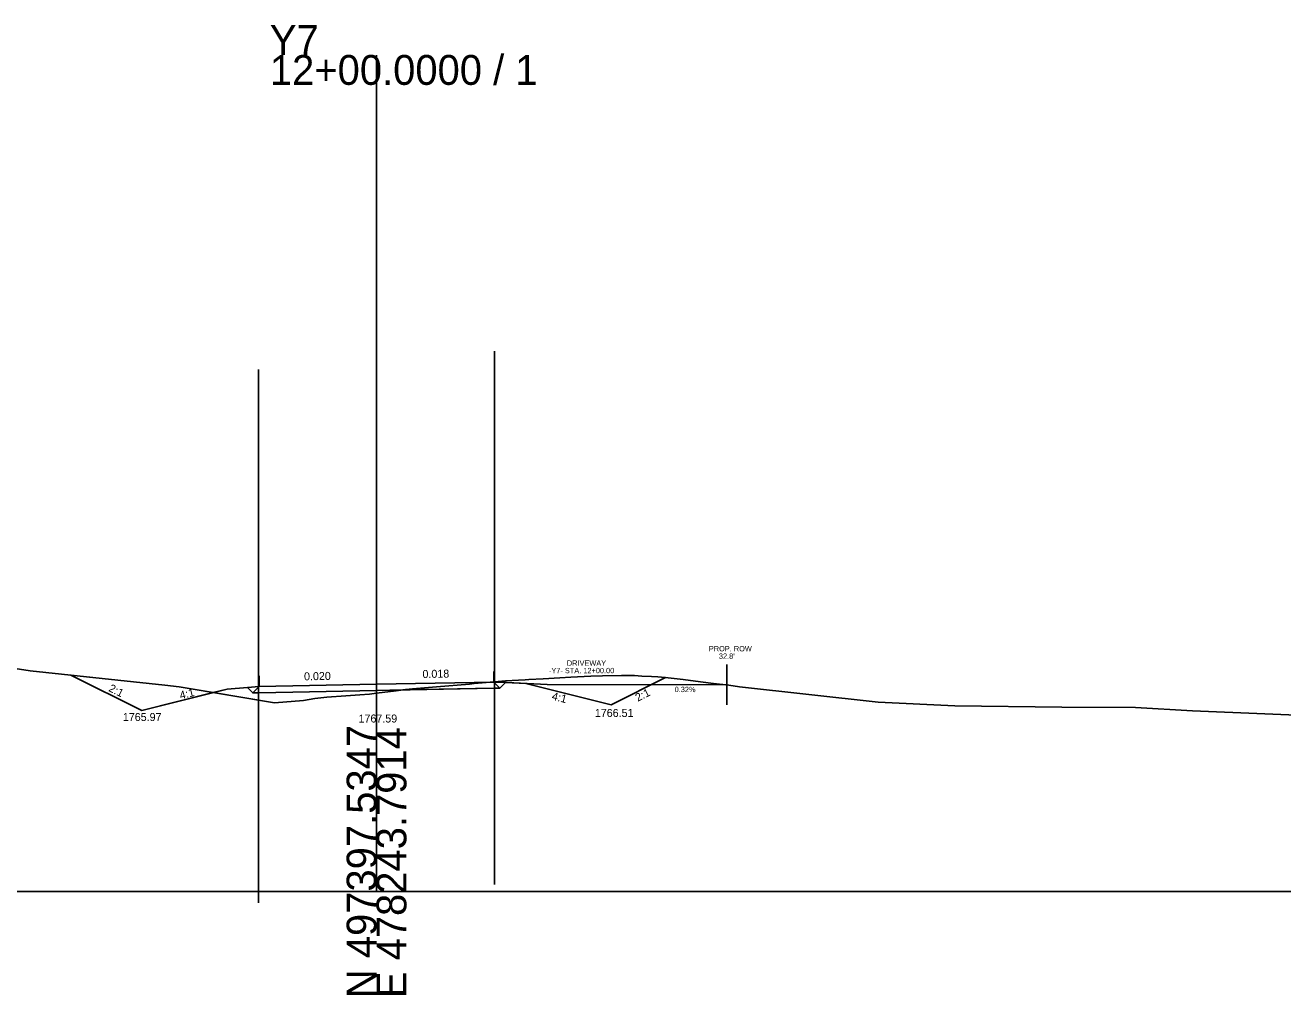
# Model space of a CAD drawing. Extents: x -26 to 403, y -10 to 4071.
# Drawn here: x 167.1 to 285, y 1990.3 to 2081.2 of the extents above; entities that cross this region are included whole.
import ezdxf

# ---------------------------------------------------------------- set-up
doc = ezdxf.new("R2010")
doc.units = 0
for name, color, linetype in [('Exist Cross Section Cell', 7, 'Continuous'), ('Exist XS Center Line Elevation Label', 7, 'Continuous'), ('Exist XS Ground Line', 7, 'Continuous'), ('Prop Road Sect_ Boring - Header (ID Tx)', 7, 'Continuous'), ('Prop Road Sect_ Boring - Material (Outline)', 7, 'Continuous'), ('Prop XS Ditch Slope Text', 7, 'Continuous'), ('Prop XS Ditch Standard Text', 7, 'Continuous'), ('Prop XS Dump Level', 7, 'Continuous'), ('Prop XS Earthwork Shape', 7, 'Continuous'), ('Prop XS EOT Tick Mark', 7, 'Continuous'), ('Prop XS Finish Grade', 7, 'Continuous'), ('Prop XS Finish Grade Earthwork', 7, 'Continuous'), ('Prop XS Finish Grade Pavement', 7, 'Continuous'), ('Prop XS Pvmt Edge Slope', 7, 'Continuous'), ('Prop XS SE Text', 7, 'Continuous'), ('Prop XS Side Slope Text', 7, 'Continuous'), ('Prop XS Subgrade Earthwork', 7, 'Continuous'), ('Scratch_Level_2', 7, 'Continuous')]:
    doc.layers.add(name, color=color, linetype=linetype)

msp = doc.modelspace()

# ---------------------------------------------------------------- linework, layer by layer
at = {"layer": 'Exist Cross Section Cell'}
for p, q in [((200, 2000), (200, 2078.42)), ((0, 2000), (200, 2000)), ((200, 2000), (400, 2000))]:
    msp.add_line(p, q, dxfattribs=at)
at = {"layer": 'Exist XS Ground Line'}
msp.add_lwpolyline([(157.4, 2022.26), (167.53, 2020.7), (180.14, 2019.35), (181.49, 2019.19), (190.45, 2017.67), (193.16, 2017.91), (194.22, 2018.08), (195.35, 2018.23), (197.11, 2018.34), (198.42, 2018.43), (199.33, 2018.51), (200, 2018.59), (201.83, 2018.82), (202.72, 2018.92), (203.36, 2018.99), (205.62, 2019.18), (208.72, 2019.45), (209.15, 2019.49), (211.41, 2019.68), (212.1, 2019.74), (213.32, 2019.81), (213.93, 2019.84), (214.29, 2019.86), (215.61, 2019.93), (217.17, 2020.02), (218.21, 2020.1), (220.08, 2020.17), (221.19, 2020.22), (222.95, 2020.24), (223.26, 2020.25), (223.63, 2020.26), (224.18, 2020.25), (224.88, 2020.19), (225.78, 2020.14), (226.38, 2020.12), (227.06, 2020.06), (228.75, 2019.86), (230.37, 2019.65), (231.58, 2019.51), (233.03, 2019.33), (234.03, 2019.18), (247.01, 2017.76), (254.19, 2017.4), (264.25, 2017.29), (271.14, 2017.25), (276.49, 2016.94), (290.78, 2016.35)], dxfattribs=at)
at = {"layer": 'Prop Road Sect_ Boring - Header (ID Tx)'}
for points in [[(211, 2019.63), (212.1, 2019.58), (211.57, 2019.06)], [(189, 2019.21), (187.9, 2019.12), (188.4, 2018.61)]]:
    msp.add_lwpolyline(points, close=True, dxfattribs=at)
at = {"layer": 'Prop Road Sect_ Boring - Material (Outline)'}
for p, q in [((232.84, 2021.28), (232.84, 2017.49)), ((211, 2019.65), (216, 2019.41)), ((216, 2019.41), (232.84, 2019.36))]:
    msp.add_line(p, q, dxfattribs=at)
at = {"layer": 'Prop XS Dump Level'}
for p, q in [((200, 2019.43), (211, 2019.63)), ((189, 2019.21), (200, 2019.43))]:
    msp.add_line(p, q, dxfattribs=at)
at = {"layer": 'Prop XS Earthwork Shape'}
for points in [[(178, 2016.97), (171.35, 2020.29), (180.14, 2019.35), (181.49, 2019.19), (184.69, 2018.64)], [(212.1, 2019.58), (214, 2019.51), (222, 2017.51), (227.09, 2020.05), (227.06, 2020.06), (226.38, 2020.12), (225.78, 2020.14), (224.88, 2020.19), (224.18, 2020.25), (223.63, 2020.26), (223.26, 2020.25), (222.95, 2020.24), (221.19, 2020.22), (220.08, 2020.17), (218.21, 2020.1), (217.17, 2020.02), (215.61, 2019.93), (214.29, 2019.86), (213.93, 2019.84), (213.32, 2019.81), (212.1, 2019.74), (211.41, 2019.68), (209.15, 2019.49), (208.72, 2019.45), (205.62, 2019.18), (203.36, 2018.99), (202.72, 2018.92), (202.45, 2018.89), (211, 2019.05), (211.57, 2019.06)], [(188.4, 2018.61), (187.9, 2019.12), (186, 2018.97), (184.69, 2018.64), (190.45, 2017.67), (193.16, 2017.91), (194.22, 2018.08), (195.35, 2018.23), (197.11, 2018.34), (198.42, 2018.43), (199.33, 2018.51), (200, 2018.59), (201.83, 2018.82), (202.45, 2018.89), (200, 2018.85), (189, 2018.63)]]:
    msp.add_lwpolyline(points, close=True, dxfattribs=at)
at = {"layer": 'Prop XS EOT Tick Mark'}
for p, q in [((211, 2019.63), (211, 2020.63)), ((189, 2019.21), (189, 2020.21))]:
    msp.add_line(p, q, dxfattribs=at)
at = {"layer": 'Prop XS Finish Grade'}
for p, q in [((211, 2019.63), (212.1, 2019.58)), ((189, 2019.21), (187.9, 2019.12))]:
    msp.add_line(p, q, dxfattribs=at)
at = {"layer": 'Prop XS Finish Grade Earthwork'}
for p, q in [((178, 2016.97), (171.35, 2020.29)), ((212.1, 2019.58), (214, 2019.51)), ((214, 2019.51), (222, 2017.51)), ((222, 2017.51), (227.09, 2020.05)), ((186, 2018.97), (178, 2016.97)), ((187.9, 2019.12), (186, 2018.97))]:
    msp.add_line(p, q, dxfattribs=at)
at = {"layer": 'Prop XS Finish Grade Pavement'}
for p, q in [((200, 2019.43), (211, 2019.63)), ((189, 2019.21), (200, 2019.43))]:
    msp.add_line(p, q, dxfattribs=at)
at = {"layer": 'Prop XS Pvmt Edge Slope'}
for p, q in [((211, 2019.63), (211.57, 2019.06)), ((189, 2019.21), (188.4, 2018.61))]:
    msp.add_line(p, q, dxfattribs=at)
at = {"layer": 'Prop XS Subgrade Earthwork'}
for p, q in [((211.57, 2019.06), (212.1, 2019.58)), ((188.4, 2018.61), (187.9, 2019.12)), ((189, 2018.63), (188.4, 2018.61)), ((200, 2018.85), (189, 2018.63)), ((211, 2019.05), (200, 2018.85)), ((211, 2019.05), (211.57, 2019.06))]:
    msp.add_line(p, q, dxfattribs=at)
at = {"layer": 'Scratch_Level_2'}
for p, q in [((211.07, 2050.65), (211.07, 2000.65)), ((188.93, 2048.92), (188.93, 1998.92))]:
    msp.add_line(p, q, dxfattribs=at)

# ---------------------------------------------------------------- texts
at = {"layer": 'Exist Cross Section Cell'}
for s, p in [('Y7', (190, 2078.42)), ('12+00.0000 / 1', (190, 2075.62))]:
    msp.add_text(s, height=2.8, dxfattribs=at).set_placement(p)
for s, p in [('N 497397.5347', (200, 1990)), ('E 478243.7914', (202.8, 1990))]:
    msp.add_text(s, height=2.8, rotation=90, dxfattribs=at).set_placement(p)
at = {"layer": 'Exist XS Center Line Elevation Label'}
msp.add_text('1767.59', height=0.75, dxfattribs=at).set_placement((198.31, 2015.84))
at = {"layer": 'Prop Road Sect_ Boring - Material (Outline)'}
for s, p in [('PROP. ROW', (231.15, 2022.51)), ("32.8'", (232.09, 2021.81)), ('-Y7- STA. 12+00.00', (216.16, 2020.46)), ('DRIVEWAY', (217.84, 2021.16))]:
    msp.add_text(s, height=0.5, dxfattribs=at).set_placement(p)
msp.add_text('0.32%', height=0.5, rotation=359.8155, dxfattribs=at).set_placement((227.94, 2018.69))
at = {"layer": 'Prop XS Ditch Slope Text'}
for rotation, p in [(14.0362, (181.64, 2018)), (345.9638, (216.38, 2017.99))]:
    msp.add_text('4:1', height=0.75, rotation=rotation, dxfattribs=at).set_placement(p)
at = {"layer": 'Prop XS Ditch Standard Text'}
for s, p in [('1766.51', (220.46, 2016.36)), ('1765.97', (176.22, 2015.98))]:
    msp.add_text(s, height=0.75, dxfattribs=at).set_placement(p)
at = {"layer": 'Prop XS Dump Level'}
for p in [(214, 2019.47), (186, 2018.93)]:
    msp.add_text('Case1', height=0.04, dxfattribs=at).set_placement(p)
at = {"layer": 'Prop XS SE Text'}
for s, rotation, p in [('0.018', 1.0503, (204.31, 2020.01)), ('0.020', 1.1458, (193.21, 2019.79))]:
    msp.add_text(s, height=0.75, rotation=rotation, dxfattribs=at).set_placement(p)
at = {"layer": 'Prop XS Side Slope Text'}
for rotation, p in [(333.4349, (174.82, 2018.81)), (26.5651, (224.48, 2017.78))]:
    msp.add_text('2:1', height=0.75, rotation=rotation, dxfattribs=at).set_placement(p)

doc.saveas('drawing.dxf')
